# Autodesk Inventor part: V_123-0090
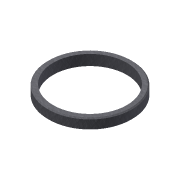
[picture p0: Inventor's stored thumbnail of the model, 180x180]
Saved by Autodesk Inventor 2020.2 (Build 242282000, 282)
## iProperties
Created: 2006-02
Part Number: V_123-0090
Document SubType Name: Modeling
Designer: F.Stasiak
Description: Tuleja dystansowa 35x40x5
Material: Stal
Project: Przekładnia X51
Density: 7.85 g/cm^3
Appearance: Stal metaliczna (obrabiana_01)
Manager: www.cadconsulting.pl
Company: Fabian Stasiak CAD Consulting
Author: F.Stasiak
Subject: Zbiór ćwiczeń. Autodesk Inventor 2020. Kurs podstawowy
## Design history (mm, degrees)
sketch "Szkic1"
  geometry: C1 r 17.5 at (0, 0); C2 r 20 at (0, 0); 1 further point
  constraints: 2 centre point, 2 coincident
  dimensions: "d0" = 35 diameter of C1; "d1" = 40 diameter of C2
extrude "Wyciągnięcie proste1" new body sketch "Szkic1" distance "d2" = 5; taper "d3" = 0 deg
chamfer "Faza1" distance "d4" = 0.5; stored, may be unused: second distance "d5" = 2, angle "d6" = 45 deg
node "Bryła1"
node "Korpusy bryłowe"
node "Korpusy powierzchniowe"
